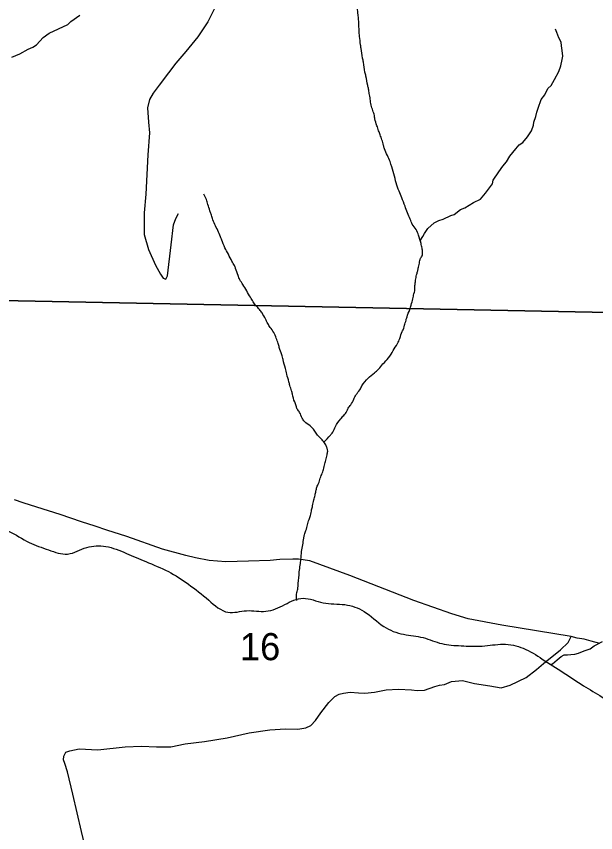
# Model space of a CAD drawing. Extents: x 0 to 191, y 0 to 55.
# Drawn here: x 148.013 to 148.459, y 20.562 to 21.192 of the extents above; entities that cross this region are included whole.
import ezdxf

# ---------------------------------------------------------------- set-up
doc = ezdxf.new("R2010")
doc.units = 0
for name, color, linetype in [('GM_X_Corporation', 7, 'Continuous'), ('GM_X_County_Road', 7, 'Continuous'), ('GM_X_Minor_River', 7, 'Continuous'), ('GM_X_Section_Text', 7, 'Continuous'), ('GM_X_Township_Road', 7, 'Continuous')]:
    doc.layers.add(name, color=color, linetype=linetype)

msp = doc.modelspace()

# ---------------------------------------------------------------- linework, layer by layer
at = {"layer": 'GM_X_Corporation'}
for points in [[(147.99507, 21.48227), (148.5062, 21.47402), (148.49568, 20.96286), (147.98775, 20.97285)], [(147.98775, 20.97285), (148.49568, 20.96286), (148.48878, 20.45041), (147.98029, 20.45945)]]:
    msp.add_lwpolyline(points, close=True, dxfattribs=at)
at = {"layer": 'GM_X_County_Road'}
msp.add_lwpolyline([(148.46272, 20.70807), (148.45596, 20.70998), (148.45044, 20.71141), (148.44521, 20.71236), (148.44045, 20.7135), (148.38714, 20.72228), (148.36106, 20.72725), (148.34844, 20.73097), (148.31915, 20.74143), (148.26988, 20.76068), (148.23904, 20.77175), (148.23014, 20.77309), (148.22579, 20.7732), (148.21596, 20.77289), (148.20851, 20.77206), (148.19164, 20.77165), (148.17418, 20.77121), (148.16131, 20.77213), (148.15092, 20.77406), (148.14329, 20.77599), (148.12527, 20.78096), (148.09796, 20.79052), (148.08233, 20.79558), (148.07341, 20.79852), (148.06302, 20.80192), (148.04657, 20.80762), (148.02855, 20.81332), (148.01797, 20.81663), (148.01126, 20.81883)], dxfattribs=at)
at = {"layer": 'GM_X_Minor_River'}
for points in [[(148.00912, 21.16002), (148.01533, 21.16258), (148.0219, 21.16628), (148.02528, 21.16785), (148.0281, 21.1696), (148.03331, 21.17518), (148.03799, 21.17848), (148.05228, 21.18514), (148.05471, 21.18746), (148.06164, 21.19249)], [(148.32488, 21.01582), (148.32436, 21.0191), (148.32603, 21.02178), (148.32732, 21.02427), (148.32991, 21.02792), (148.33496, 21.03236), (148.33853, 21.03412), (148.34173, 21.03512), (148.34774, 21.03805), (148.35038, 21.03885), (148.35524, 21.04253), (148.35844, 21.0439), (148.36519, 21.04799), (148.37046, 21.05053), (148.37455, 21.05534), (148.37993, 21.06244), (148.38046, 21.0653), (148.38472, 21.07163), (148.38768, 21.07604), (148.39066, 21.07931), (148.39325, 21.08372), (148.39771, 21.0893), (148.4005, 21.09237), (148.40312, 21.09431), (148.40684, 21.09854), (148.40999, 21.10334), (148.41144, 21.10754), (148.41179, 21.11001), (148.41324, 21.11421), (148.41395, 21.11764), (148.41504, 21.1207), (148.4174, 21.12738), (148.42018, 21.13103), (148.42257, 21.13582), (148.42519, 21.13832), (148.42758, 21.14273), (148.43109, 21.14905), (148.43253, 21.15344), (148.4336, 21.1582), (148.43394, 21.16087), (148.4335, 21.16523), (148.43307, 21.16883), (148.43265, 21.17168), (148.4309, 21.17488), (148.42932, 21.17904), (148.42834, 21.18169)], [(148.42442, 20.69227), (148.42621, 20.69253), (148.42976, 20.69562), (148.43276, 20.69813), (148.4352, 20.6995), (148.43766, 20.69953), (148.4403, 20.69976), (148.44333, 20.69999), (148.44616, 20.7006), (148.45048, 20.70256), (148.45519, 20.70415), (148.45818, 20.70647), (148.46475, 20.7098)]]:
    msp.add_lwpolyline(points, dxfattribs=at)
for points in [[(148.24976, 20.86339), (148.25479, 20.86869), (148.25667, 20.87098), (148.25873, 20.87537), (148.26286, 20.88128), (148.26512, 20.88395), (148.26757, 20.8872), (148.2685, 20.88948), (148.27057, 20.89215), (148.27281, 20.89635), (148.27469, 20.89997), (148.27751, 20.90359), (148.27919, 20.90683), (148.2839, 20.91256), (148.2888, 20.91677), (148.29201, 20.91964), (148.29539, 20.92365), (148.29973, 20.92824), (148.30329, 20.93396), (148.30648, 20.9393), (148.30835, 20.9433), (148.31021, 20.94862), (148.31152, 20.9511), (148.31207, 20.95338), (148.31319, 20.95738), (148.31393, 20.95985), (148.31597, 20.96556), (148.31709, 20.96899), (148.31838, 20.97374), (148.3193, 20.97774), (148.31986, 20.98002), (148.31984, 20.98249), (148.3202, 20.98553), (148.32056, 20.98819), (148.32129, 20.99218), (148.32203, 20.99484), (148.32258, 20.99731), (148.3235, 21.00131), (148.32443, 21.00511), (148.32574, 21.0074), (148.32591, 21.00987), (148.32551, 21.0129), (148.32473, 21.01651), (148.32279, 21.02276), (148.32105, 21.02712), (148.31798, 21.03127), (148.31644, 21.03525), (148.31432, 21.03998), (148.31238, 21.04529), (148.30987, 21.05153), (148.30775, 21.05684), (148.30562, 21.06309), (148.30386, 21.0701), (148.30153, 21.07749), (148.29998, 21.08185), (148.29883, 21.08431), (148.29651, 21.08942), (148.29574, 21.09207), (148.29457, 21.09643), (148.29321, 21.10022), (148.29205, 21.10325), (148.2907, 21.10723), (148.28914, 21.11253), (148.28875, 21.115), (148.28758, 21.11898), (148.28622, 21.12315), (148.28562, 21.1277), (148.28483, 21.13206), (148.28424, 21.13547), (148.28365, 21.13813), (148.28227, 21.14552), (148.28149, 21.14856), (148.2803, 21.15614), (148.27971, 21.15937), (148.27852, 21.16676), (148.27812, 21.16961), (148.27732, 21.17606), (148.27711, 21.17834), (148.27688, 21.18327), (148.27668, 21.18555), (148.27666, 21.18783), (148.27625, 21.192), (148.27611, 21.21288), (148.27628, 21.21535), (148.27663, 21.21972), (148.27848, 21.226), (148.28055, 21.22943), (148.28129, 21.23247), (148.28258, 21.23704), (148.2837, 21.24008), (148.28576, 21.24409), (148.28726, 21.24694), (148.28913, 21.25113), (148.29025, 21.2538), (148.29136, 21.25722), (148.29341, 21.26217), (148.29508, 21.26731)], [(148.22891, 20.74134), (148.22889, 20.74736), (148.22981, 20.75098), (148.22998, 20.75364), (148.23015, 20.75611), (148.23069, 20.76048), (148.23086, 20.76333), (148.23158, 20.76865), (148.23212, 20.77283), (148.23265, 20.7791), (148.23356, 20.78424), (148.23428, 20.78937), (148.23483, 20.79203), (148.23595, 20.79527), (148.23725, 20.79964), (148.23836, 20.80383), (148.23947, 20.80687), (148.24039, 20.81125), (148.24113, 20.81429), (148.24205, 20.81885), (148.24297, 20.82247), (148.24371, 20.8257), (148.24445, 20.82856), (148.24575, 20.8316), (148.24705, 20.8356), (148.24854, 20.83941), (148.24984, 20.8434), (148.25021, 20.84569), (148.25132, 20.84949), (148.25224, 20.85367), (148.25279, 20.85634), (148.2524, 20.85861), (148.25124, 20.86126), (148.24913, 20.86429), (148.24607, 20.86749), (148.24396, 20.87014), (148.23918, 20.87599), (148.23498, 20.87919), (148.23307, 20.88184), (148.23114, 20.88619), (148.22922, 20.88884), (148.22845, 20.8913), (148.22729, 20.89433), (148.22554, 20.9004), (148.22495, 20.90286), (148.22359, 20.90703), (148.22282, 20.90987), (148.22126, 20.91575), (148.22028, 20.92011), (148.21833, 20.92693), (148.21736, 20.93072), (148.21542, 20.93622), (148.21464, 20.93925), (148.21309, 20.94342), (148.21116, 20.94796), (148.20848, 20.95174), (148.20656, 20.95477), (148.20483, 20.95837), (148.20214, 20.9629), (148.20023, 20.96555), (148.19736, 20.96857), (148.19525, 20.97159), (148.19314, 20.975), (148.18738, 20.98483), (148.18508, 20.98842), (148.18372, 20.99183), (148.18179, 20.99714), (148.18082, 20.99941), (148.1789, 21.00281), (148.17621, 21.00811), (148.17352, 21.01322), (148.17101, 21.01909), (148.17004, 21.02155), (148.16811, 21.02648), (148.16561, 21.03121), (148.16387, 21.03575), (148.1629, 21.03897), (148.16193, 21.04162), (148.16038, 21.04655), (148.15922, 21.05034), (148.15729, 21.0545)], [(147.62125, 20.73946), (147.63766, 20.74147), (147.65188, 20.74195), (147.66817, 20.74699), (147.68255, 20.75222), (147.6975, 20.75802), (147.71436, 20.76193), (147.72991, 20.76374), (147.74506, 20.7686), (147.76021, 20.77288), (147.77612, 20.77716), (147.79147, 20.77973), (147.80607, 20.78078), (147.82181, 20.78241), (147.83677, 20.78707), (147.85117, 20.78925), (147.86594, 20.79353), (147.8811, 20.79724), (147.89626, 20.79943), (147.9122, 20.80068), (147.92832, 20.80098), (147.94313, 20.80013), (147.96078, 20.80006), (147.97615, 20.80016), (147.99152, 20.79913), (148.00673, 20.79467), (148.02254, 20.78605), (148.03757, 20.78026), (148.05221, 20.77713), (148.06697, 20.78217), (148.08158, 20.78302), (148.09755, 20.77762), (148.1124, 20.77127), (148.12991, 20.7636), (148.14535, 20.75383), (148.16099, 20.74159), (148.17586, 20.73219), (148.19027, 20.73343), (148.20508, 20.73296), (148.21965, 20.73818), (148.23385, 20.74303), (148.24924, 20.73952), (148.26595, 20.73812), (148.28079, 20.7329), (148.29605, 20.72122), (148.31127, 20.71525), (148.32628, 20.71269), (148.34073, 20.70804), (148.35555, 20.70643), (148.37187, 20.70616), (148.38799, 20.7076), (148.40357, 20.70447), (148.41824, 20.69621), (148.43444, 20.68588), (148.45007, 20.67553), (148.46436, 20.66689), (148.47925, 20.65465), (148.49376, 20.64164), (148.50826, 20.62958), (148.52581, 20.61659), (148.54029, 20.60928), (148.55567, 20.60749), (148.57068, 20.60455), (148.58551, 20.60028), (148.60262, 20.59602), (148.61975, 20.58835), (148.63441, 20.58104), (148.65002, 20.57373), (148.6643, 20.5668), (148.67858, 20.55949), (148.6942, 20.5518), (148.70904, 20.54563), (148.72484, 20.53909), (148.73911, 20.53349), (148.75375, 20.52922), (148.76823, 20.52038), (148.7829, 20.51174), (148.7977, 20.51203), (148.8127, 20.51061), (148.82846, 20.50958), (148.84288, 20.50967), (148.85749, 20.50958), (148.87287, 20.50759), (148.88883, 20.50466), (148.90365, 20.5019), (148.91943, 20.4984), (148.93559, 20.49395), (148.94986, 20.48777), (148.96475, 20.47552), (148.98057, 20.46518), (148.99483, 20.46071), (149.01123, 20.45037), (149.02707, 20.43623), (149.04195, 20.42588), (149.05661, 20.41894), (149.07085, 20.41695), (149.08525, 20.42065)]]:
    msp.add_spline(points, degree=3, dxfattribs=at)
at = {"layer": 'GM_X_Township_Road'}
for points in [[(148.16538, 21.19755), (148.16025, 21.18739), (148.15418, 21.17801)], [(148.15418, 21.17801), (148.15267, 21.17566), (148.14337, 21.16447), (148.13574, 21.1554), (148.12999, 21.14789), (148.12275, 21.13844), (148.1183, 21.13228), (148.11535, 21.12729), (148.11394, 21.12099), (148.11452, 21.10998), (148.11524, 21.10163), (148.11402, 21.08488), (148.11247, 21.05445), (148.11121, 21.03998), (148.11132, 21.02326), (148.11457, 21.01173), (148.1201, 20.99985), (148.12384, 20.9927), (148.12579, 20.98969), (148.12789, 20.98897), (148.12918, 20.99146), (148.13198, 21.01546), (148.13379, 21.0307), (148.13561, 21.03567), (148.13781, 21.03951)], [(148.06542, 20.55236), (148.06295, 20.56315), (148.05635, 20.59212), (148.05205, 20.60934), (148.05004, 20.61577), (148.04904, 20.61841), (148.04936, 20.62146), (148.05083, 20.62453), (148.05404, 20.62554), (148.06104, 20.62699), (148.0755, 20.62611), (148.09654, 20.6284), (148.10926, 20.62901), (148.12086, 20.62865), (148.13188, 20.62846), (148.14286, 20.63075), (148.15764, 20.63273), (148.17526, 20.63552), (148.19229, 20.63944), (148.20821, 20.64163), (148.22016, 20.64242), (148.22967, 20.64202), (148.23288, 20.64265), (148.23592, 20.64308), (148.23987, 20.64487), (148.24342, 20.64873), (148.24749, 20.6547), (148.25361, 20.6628), (148.25828, 20.66725), (148.26148, 20.66921), (148.26507, 20.66985), (148.27019, 20.6707), (148.27647, 20.67024), (148.28141, 20.66995), (148.28881, 20.67066), (148.29789, 20.67253), (148.30738, 20.67308), (148.31746, 20.6725), (148.32184, 20.67201), (148.32734, 20.6723), (148.33528, 20.67492), (148.33906, 20.67593), (148.34285, 20.67657), (148.34833, 20.67892), (148.35661, 20.67974), (148.36593, 20.67726), (148.37773, 20.67561), (148.38659, 20.67394), (148.39339, 20.67616), (148.40567, 20.68202), (148.41388, 20.68812), (148.41912, 20.69278), (148.43227, 20.70334), (148.43806, 20.70883), (148.44045, 20.7135)]]:
    msp.add_lwpolyline(points, dxfattribs=at)

# ---------------------------------------------------------------- texts
at = {"layer": 'GM_X_Section_Text'}
msp.add_text('16', height=0.020928, rotation=0.00001, dxfattribs=at).set_placement((148.18504, 20.69529))

doc.saveas('drawing.dxf')
